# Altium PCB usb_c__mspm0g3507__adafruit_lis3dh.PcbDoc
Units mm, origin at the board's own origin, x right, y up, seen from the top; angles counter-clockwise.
Board outline 92 x 60 mm, 2 copper layers (Top, Bottom), stack 0 mm thick; 36 components, 30 nets, 196 pads, 60 vias.
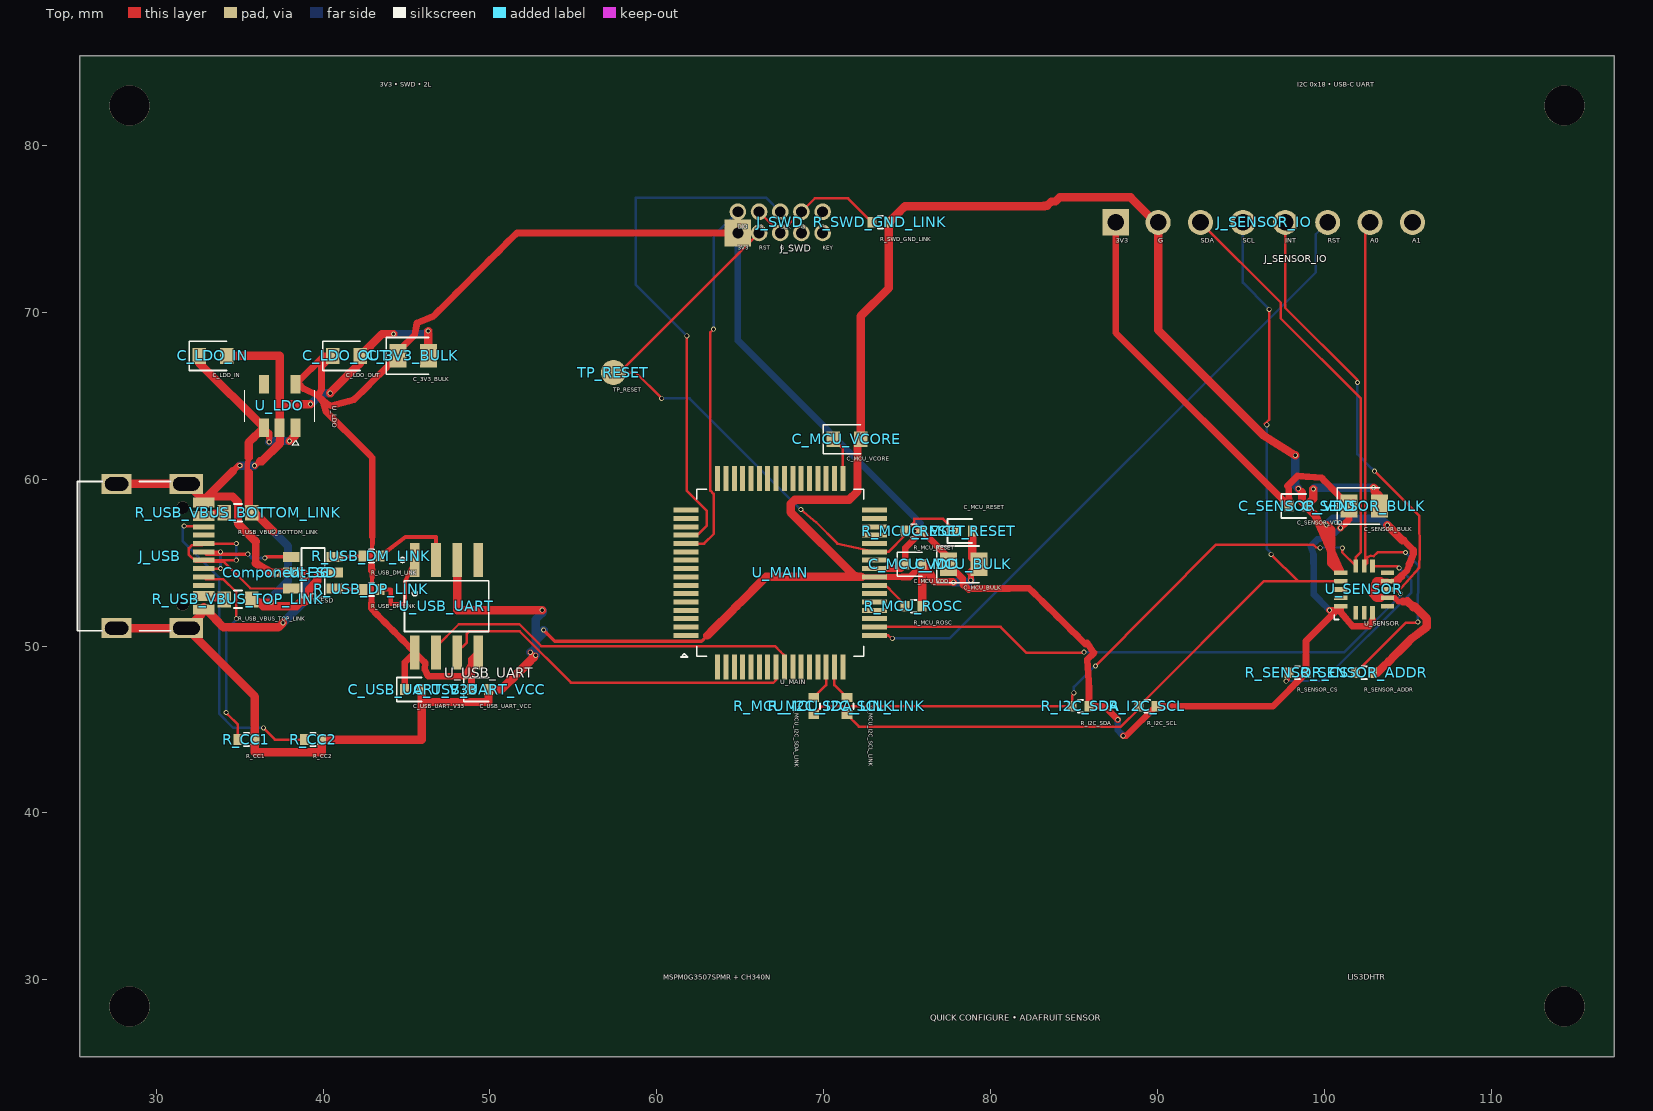
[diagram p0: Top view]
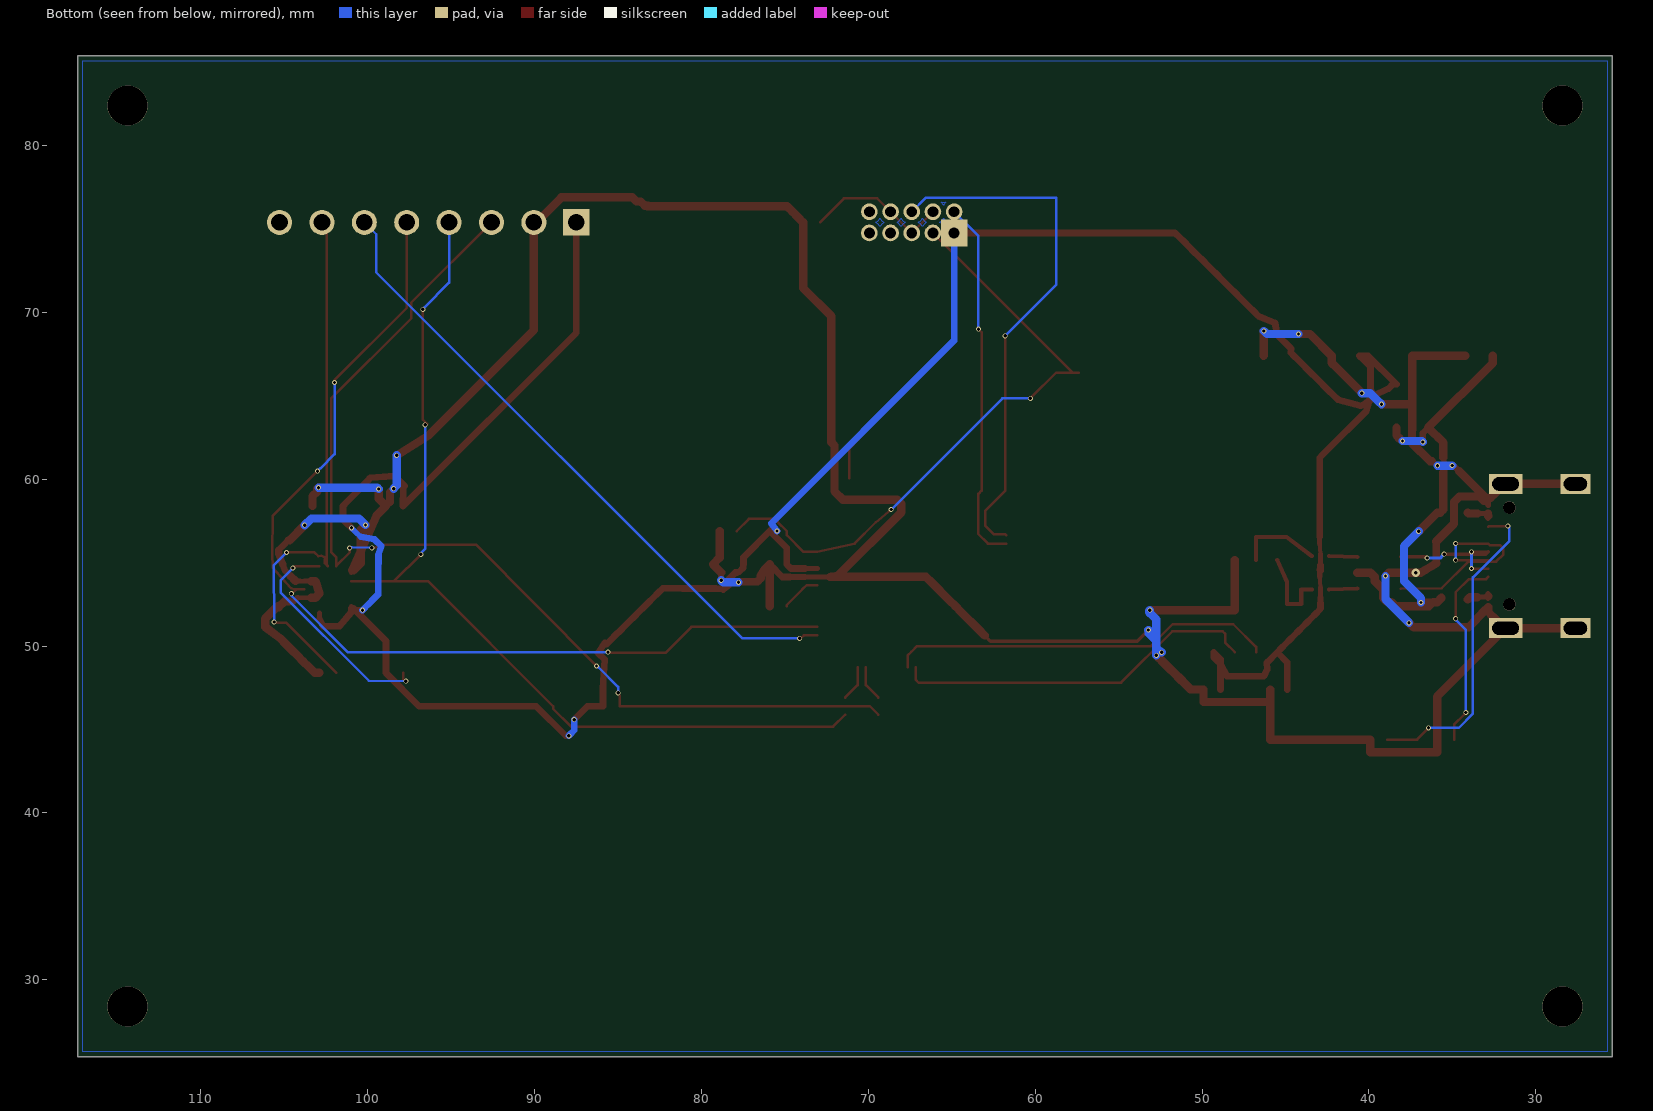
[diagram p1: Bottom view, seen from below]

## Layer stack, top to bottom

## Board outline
25.4,85.4 117.4,85.4 117.4,25.4 25.4,25.4

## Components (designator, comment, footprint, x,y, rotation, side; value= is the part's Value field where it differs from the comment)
C_3V3_BULK "" TSCIRCUIT-2.8500x1.4000mm 45.4,67.4 r0 top
C_LDO_IN "" TSCIRCUIT-2.4500x0.9500mm 33.4,67.4 r0 top
C_LDO_OUT "" TSCIRCUIT-2.4500x0.9500mm 41.4,67.4 r0 top
C_MCU_BULK "" TSCIRCUIT-2.8500x1.4000mm 78.4,54.9 r0 top
C_MCU_RESET "" TSCIRCUIT-1.5600x0.6400mm 78.4,56.9 r0 top
C_MCU_VCORE "" TSCIRCUIT-2.4500x0.9500mm 71.4,62.4 r0 top
C_MCU_VDD "" TSCIRCUIT-1.5600x0.6400mm 75.4,54.9 r0 top
C_SENSOR_BULK "" TSCIRCUIT-2.8500x1.4000mm 102.4,58.4 r0 top
C_SENSOR_VDD "" TSCIRCUIT-1.5600x0.6400mm 98.4,58.4 r0 top
C_USB_UART_V33 "" TSCIRCUIT-1.5600x0.6400mm 45.4,47.4 r0 top
C_USB_UART_VCC "" TSCIRCUIT-1.5600x0.6400mm 49.4,47.4 r0 top
Component-36 "" TSCIRCUIT-0.5000x0.5000mm 37.2,54.4 r0 top
J_SENSOR_IO "" TSCIRCUIT-19.2800x1.5000mm 96.4,75.4 r0 top
J_SWD "" TSCIRCUIT-6.0800x2.2700mm 67.4,75.4 r0 top
J_USB "" TSCIRCUIT-6.7732x9.8502mm 30.113,55.4 r90 top
R_CC1 "" TSCIRCUIT-1.5600x0.6400mm 35.4,44.4 r0 top
R_CC2 "" TSCIRCUIT-1.5600x0.6400mm 39.4,44.4 r0 top
R_I2C_SCL "" TSCIRCUIT-1.5600x0.6400mm 89.4,46.4 r0 top
R_I2C_SDA "" TSCIRCUIT-1.5600x0.6400mm 85.4,46.4 r0 top
R_MCU_I2C_SCL_LINK "" TSCIRCUIT-0.6400x1.5600mm 71.4,46.4 r270 top
R_MCU_I2C_SDA_LINK "" TSCIRCUIT-0.6400x1.5600mm 69.4,46.4 r270 top
R_MCU_RESET "" TSCIRCUIT-1.5600x0.6400mm 75.4,56.9 r0 top
R_MCU_ROSC "" TSCIRCUIT-1.5600x0.6400mm 75.4,52.4 r0 top
R_SENSOR_ADDR "" TSCIRCUIT-1.5600x0.6400mm 102.4,48.4 r0 top
R_SENSOR_CS "" TSCIRCUIT-1.5600x0.6400mm 98.4,48.4 r0 top
R_SWD_GND_LINK "" TSCIRCUIT-1.5600x0.6400mm 73.4,75.4 r0 top
R_USB_DM_LINK "" TSCIRCUIT-1.5600x0.6400mm 42.9,55.4 r0 top
R_USB_DP_LINK "" TSCIRCUIT-1.5600x0.6400mm 42.9,53.4 r0 top
R_USB_VBUS_BOTTOM_LINK "" TSCIRCUIT-2.4500x0.9500mm 34.9,58 r0 top
R_USB_VBUS_TOP_LINK "" TSCIRCUIT-2.4500x0.9500mm 34.9,52.8 r0 top
TP_RESET "" TSCIRCUIT-1.5000x1.5000mm 57.4,66.4 r0 top
U_ESD "" TSCIRCUIT-3.6000x2.5000mm 39.4,54.4 r0 top
U_LDO "" TSCIRCUIT-2.5000x3.7000mm 37.4,64.4 r270 top
U_MAIN "" TSCIRCUIT-12.8000x12.8000mm 67.4,54.4 r0 top
U_SENSOR "" TSCIRCUIT-3.6001x3.5998mm 102.4,53.4 r0 top
U_USB_UART "" TSCIRCUIT-4.3840x7.5712mm 47.4,52.4 r0 top

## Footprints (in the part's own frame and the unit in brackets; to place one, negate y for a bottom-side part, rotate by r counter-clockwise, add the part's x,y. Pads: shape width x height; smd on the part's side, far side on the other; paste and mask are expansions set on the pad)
TSCIRCUIT-0.5000x0.5000mm [mm]
TSCIRCUIT-0.6400x1.5600mm [mm]
  rect 0.54x0.64 smd: 1(-0.51,0) 2(0.51,0)
  silkscreen extent -0.15,-0.38 0.15,0.38
TSCIRCUIT-1.5000x1.5000mm [mm]
  round 1.5 smd: 1(0,0)
TSCIRCUIT-1.5600x0.6400mm [mm]
  rect 0.54x0.64 smd: 1(-0.51,0) 2(0.51,0)
  silkscreen extent -0.98,-0.72 0.51,0.72
TSCIRCUIT-2.4500x0.9500mm [mm]
  rect 0.8x0.95 smd: 1(-0.825,0) 2(0.825,0)
  silkscreen extent -1.42,-0.87 0.82,0.87
TSCIRCUIT-2.5000x3.7000mm [mm]
  rect 1.1x0.6 smd: 1(1.3,0.95) 2(1.3,0) 3(1.3,-0.95) 4(-1.3,-0.95) 5(-1.3,0.95)
  silkscreen extent -0.95,-2.1 2.35,2.1
TSCIRCUIT-2.8500x1.4000mm [mm]
  rect 1.025x1.4 smd: 1(-0.913,0) 2(0.913,0)
  silkscreen extent -1.63,-1.1 0.91,1.1
TSCIRCUIT-3.6000x2.5000mm [mm]
  rect 1x0.6 smd: 1(-1.3,-0.95) 2(-1.3,0) 3(-1.3,0.95) 4(1.3,0.95) 5(1.3,0) 6(1.3,-0.95)
  silkscreen extent -0.7,-1.49 0.7,1.49
TSCIRCUIT-3.6001x3.5998mm [mm]
  rect 0.8x0.28 smd: 1(-1.4,-1) 2(-1.4,-0.5) 3(-1.4,0) 4(-1.4,0.5) 5(-1.4,1) 9(1.4,1) 10(1.4,0.5) 11(1.4,0) 12(1.4,-0.5) 13(1.4,-1)
  rect 0.28x0.8 smd: 6(-0.5,1.4) 7(0,1.4) 8(0.5,1.4) 14(0.5,-1.4) 15(0,-1.4) 16(-0.5,-1.4)
  silkscreen extent -1.8,-1.8 -1.52,-1.52
TSCIRCUIT-4.3840x7.5712mm [mm]
  rect 0.574x2.036 smd: 1(-1.905,2.768) 2(-0.635,2.768) 3(0.635,2.768) 4(1.905,2.768) 5(1.905,-2.768) 6(0.635,-2.768) 7(-0.635,-2.768) 8(-1.905,-2.768)
  silkscreen extent -2.79,-1.52 2.53,2.92
TSCIRCUIT-6.0800x2.2700mm [mm]
  rect 1.6x1.6 hole 0.65: 1(-2.54,-0.635)
  round 1 hole 0.65: 2(-2.54,0.635) 3(-1.27,0.635) 4(0,0.635) 5(1.27,0.635) 6(2.54,0.635) 7(2.54,-0.635) 8(1.27,-0.635) 9(0,-0.635) 10(-1.27,-0.635)
TSCIRCUIT-6.7732x9.8502mm [mm]
  rect 0.3x1.3 smd: 1(-3.35,-2.737) 2(-3.05,-2.737) 3(-2.55,-2.737) 4(-2.25,-2.737) 5(-1.75,-2.737) 6(-1.25,-2.737) 7(-0.75,-2.737) 8(-0.25,-2.737) 9(0.25,-2.737) 10(0.75,-2.737) 11(1.25,-2.737) 12(1.75,-2.737) 13(2.55,-2.737) 14(2.25,-2.737) 15(3.35,-2.737) 16(3.05,-2.737)
  rect 1.2x2 hole 0.8 slot 1.6 at 90 deg: 17(-4.325,-1.693) 18(4.325,-1.693)
  rect 1.2x1.8 hole 0.8 slot 1.4 at 90 deg: 19(4.325,2.487) 20(-4.325,2.487)
  round 0.75 hole 0.75 unplated: NPTH-1(-2.9,-1.468) NPTH-2(2.9,-1.468)
  silkscreen extent -4.47,-0.75 4.47,4.83
TSCIRCUIT-12.8000x12.8000mm [mm]
  rect 1.5x0.3 smd: 1(-5.65,-3.75) 2(-5.65,-3.25) 3(-5.65,-2.75) 4(-5.65,-2.25) 5(-5.65,-1.75) 6(-5.65,-1.25) 7(-5.65,-0.75) 8(-5.65,-0.25) 9(-5.65,0.25) 10(-5.65,0.75) 11(-5.65,1.25) 12(-5.65,1.75) 13(-5.65,2.25) 14(-5.65,2.75) 15(-5.65,3.25) 16(-5.65,3.75) 33(5.65,3.75) 34(5.65,3.25) 35(5.65,2.75) 36(5.65,2.25) 37(5.65,1.75) 38(5.65,1.25) 39(5.65,0.75) 40(5.65,0.25) 41(5.65,-0.25) 42(5.65,-0.75) 43(5.65,-1.25) 44(5.65,-1.75) 45(5.65,-2.25) 46(5.65,-2.75) 47(5.65,-3.25) 48(5.65,-3.75)
  rect 0.3x1.5 smd: 17(-3.75,5.65) 18(-3.25,5.65) 19(-2.75,5.65) 20(-2.25,5.65) 21(-1.75,5.65) 22(-1.25,5.65) 23(-0.75,5.65) 24(-0.25,5.65) 25(0.25,5.65) 26(0.75,5.65) 27(1.25,5.65) 28(1.75,5.65) 29(2.25,5.65) 30(2.75,5.65) 31(3.25,5.65) 32(3.75,5.65) 49(3.75,-5.65) 50(3.25,-5.65) 51(2.75,-5.65) 52(2.25,-5.65) 53(1.75,-5.65) 54(1.25,-5.65) 55(0.75,-5.65) 56(0.25,-5.65) 57(-0.25,-5.65) 58(-0.75,-5.65) 59(-1.25,-5.65) 60(-1.75,-5.65) 61(-2.25,-5.65) 62(-2.75,-5.65) 63(-3.25,-5.65) 64(-3.75,-5.65)
  silkscreen extent -5.95,-5.05 5,5
TSCIRCUIT-19.2800x1.5000mm [mm]
  rect 1.6x1.6 hole 1: 1(-8.89,0)
  round 1.5 hole 1: 2(-6.35,0) 3(-3.81,0) 4(-1.27,0) 5(1.27,0) 6(3.81,0) 7(6.35,0) 8(8.89,0)

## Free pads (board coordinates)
  round 2.4 hole 2.4 unplated: NPTH-3(28.4,28.4) NPTH-4(114.4,28.4) NPTH-5(28.4,82.4) NPTH-6(114.4,82.4)

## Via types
v1: diameter 0.3, hole 0.2, Top to Bottom, 59 vias
v2: diameter 0.5, hole 0.2, Top to Bottom, 1 vias

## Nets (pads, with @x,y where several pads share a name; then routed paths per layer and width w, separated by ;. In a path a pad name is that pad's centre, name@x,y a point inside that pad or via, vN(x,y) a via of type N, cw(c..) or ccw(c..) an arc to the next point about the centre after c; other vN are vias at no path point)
".J_SWD > .pin2 to .U_MAIN > .pin12": J_SWD.2 U_MAIN.12 | length 22
  Top w0.15: U_MAIN.12 62.836,56.15 63.412,56.726 63.404,59.125 63.215,59.325 63.217,68.817 v1(63.4,69)
  Bottom w0.15: v1(63.4,69) 63.4,69.14 63.4,74.575 J_SWD.2
".J_SWD > .pin4 to .U_MAIN > .pin13": J_SWD.4 U_MAIN.13 | length 31.9
  Top w0.15: U_MAIN.13 61.811,56.711 62.49,56.711 63.008,57.229 63.008,58.102 61.8,59.31 v1(61.8,68.6)
  Bottom w0.15: v1(61.8,68.6) 61.756,68.644 58.745,71.655 58.745,76.868 66.567,76.868 J_SWD.4
".U_MAIN > .pin42 to .R_MCU_ROSC > .pin1": R_MCU_ROSC.1 U_MAIN.42 | length 2.4
  Top w0.15: U_MAIN.42 73.701,53.651 73.958,53.413 74.89,52.46 R_MCU_ROSC.1
GND: C_3V3_BULK.2 C_LDO_IN.2 C_LDO_OUT.2 C_MCU_BULK.2 C_MCU_RESET.2 C_MCU_VCORE.2 C_MCU_VDD.2 C_SENSOR_BULK.2 C_SENSOR_VDD.2 C_USB_UART_V33.2 C_USB_UART_VCC.2 J_SENSOR_IO.2 J_USB.1 J_USB.2 J_USB.15 J_USB.16 J_USB.17 J_USB.18 J_USB.19 J_USB.20 R_CC1.2 R_CC2.2 R_MCU_ROSC.2 R_SENSOR_ADDR.2 R_SWD_GND_LINK.2 U_ESD.2 U_LDO.2 U_MAIN.41 U_SENSOR.5 U_SENSOR.10 U_SENSOR.12 U_USB_UART.3 | length 241.6
  Top w0.2: v1(53.215,50.967) 53.554,50.628 53.893,50.289 54.381,50.289 54.87,50.289 55.358,50.289 55.846,50.289 56.334,50.289 56.823,50.289 57.311,50.289 57.799,50.289 58.288,50.289 58.776,50.289 59.264,50.289 59.752,50.289 60.241,50.289 60.729,50.289 61.217,50.289 61.706,50.289 62.194,50.289 62.682,50.289 63.033,50.64
  Top w0.275: J_USB.16 J_USB.15@33.109,58.71
  Top w0.28: U_SENSOR.5@100.86,54.54 U_SENSOR.5 U_SENSOR.5@100.938,54.54 ; U_SENSOR.12@103.4,52.9 U_SENSOR.12 103.988,52.9 104.081,52.9 104.175,52.9 U_SENSOR.12@104.2,52.9 ; U_SENSOR.10@103.4,53.9 U_SENSOR.10 104.069,53.9 104.338,53.9
  Top w0.3: J_USB.1@32.699,51.9 J_USB.1 J_USB.1@32.849,52.2 ; J_USB.15@32.699,58.9 J_USB.15 ; J_USB.2 J_USB.1@32.994,52.2 ; J_USB.16@32.849,58.6 J_USB.15 ; J_USB.15@32.999,58.9 J_USB.15 ; U_MAIN.41@73.8,54.15 73.706,54.15 73.612,54.15 73.519,54.15 73.425,54.15 73.331,54.15 73.237,54.15 73.144,54.15 U_MAIN.41 ; U_MAIN.41 72.627,54.15 72.3,54.15 72.585,54.15 U_MAIN.41
  Top w0.325: J_USB.16 J_USB.16@32.849,58.6 ; v1(35.89,60.817) 35.911,60.796 v1@35.913,60.796 ; v1(52.425,49.625) v1@52.64,49.349 ; 52.617,49.315 52.617,49.325 v1(52.74,49.449) ; 104.252,52.873 104.315,52.798 104.387,52.735 104.458,52.682
  Top w0.35: v1@35.913,60.796 36.216,61.092 ; 104.2,52.9 104.225,52.9 104.252,52.873
  Top w0.375: 34.578,60.479 34.924,60.825 v1(35.007,60.825) ; U_MAIN.41@73.8,54.15 74.253,54.15 74.707,54.15 ; v1(78.825,53.948) C_MCU_BULK.2@78.825,54.413 ; v1(98.454,59.443) 98.674,59.223 ; 104.458,52.682 104.46,52.682 104.725,52.682 ; 104.65,54.213 104.963,54.525 105.087,54.858 ; 104.775,56.337 105.056,56.056 105.338,55.775
  Top w0.4: 37.2,54.4 U_ESD.2@37.6,54.4 ; 74.707,54.15 75.16,54.15 75.41,54.4 75.66,54.65 C_MCU_VDD.2
  Top w0.425: C_SENSOR_VDD.2@98.674,58.636 C_SENSOR_VDD.2 ; 105.087,54.858 105.212,55.192 105.338,55.525 105.338,55.775
  Top w0.437: 35.963,55.4 35.963,55.838 35.963,56.275
  Top w0.45: 35.963,54.963 35.963,55.4 ; 76.65,53.869 76.946,53.864 77.338,53.864 77.73,53.864 77.749,53.86 v1(77.781,53.828) ; 104.693,56.337 104.775,56.337
  Top w0.475: 71.656,54.15 72.12,54.15 72.3,54.15 72.205,54.15 ; 76.453,54.066 76.65,53.869 ; 104.338,53.9 104.65,54.213 ; 104.725,52.682 104.991,52.682
  Top w0.5: J_USB.20 J_USB.17 ; J_USB.19 J_USB.18 31.874,59.725 32.474,59.125 32.699,58.9 ; 32.699,51.9 32.474,51.675 31.874,51.075 J_USB.17 ; J_USB.1@32.849,52.2 J_USB.2 ; J_USB.1@32.994,52.2 34.028,51.131 37.321,51.131 v1(37.592,51.402) ; 32.999,58.9 34.578,60.479 ; J_USB.15@33.109,58.71 33.368,58.969 34.581,58.969 34.9,58.65 34.9,57.338 35.963,56.275 ; C_LDO_IN.2 37.4,67.4 U_LDO.2 ; 35.963,54.963 36.274,54.775 36.586,54.588 36.897,54.4 37.2,54.4 38.8,54.4 v1(39,54.2) ; 36.216,61.092 36.342,61.092 37.4,62.15 37.414,62.686 U_LDO.2 ; v1(39.244,64.505) 37.4,64.505 U_LDO.2 ; v1(40.421,65.166) 40.416,65.166 40.422,65.17 40.723,65.471 41.023,65.773 41.324,66.075 41.624,66.377 41.925,66.679 42.225,66.981 C_LDO_OUT.2 43.534,68.709 v1(44.222,68.709) ; v1(46.293,68.892) 46.293,67.419 C_3V3_BULK.2 ; U_USB_UART.3 48.035,52.154 v1(53.131,52.154) ; 52.617,49.315 52.297,48.996 51.978,48.677 51.659,48.358 51.34,48.038 51.021,47.719 50.702,47.4 50.306,47.4 C_USB_UART_VCC.2 ; v1@52.64,49.349 52.603,49.349 52.278,49.024 51.953,48.699 51.628,48.374 51.304,48.05 50.979,47.725 50.654,47.4 50.282,47.4 C_USB_UART_VCC.2 ; 63.033,50.64 63.384,50.991 63.735,51.342 64.086,51.693 64.437,52.044 64.788,52.395 65.139,52.746 65.49,53.097 65.841,53.448 66.192,53.799 66.543,54.15 67.008,54.15 67.473,54.15 67.937,54.15 68.402,54.15 68.867,54.15 69.332,54.15 69.797,54.15 70.261,54.15 70.726,54.15 71.191,54.15 71.656,54.15 ; 72.205,54.15 71.994,54.15 71.947,54.197 71.853,54.197 68.025,58.025 68.025,58.525 68.275,58.775 71.525,58.775 72.025,59.275 72.025,62.025 72.225,62.225 C_MCU_VCORE.2 72.225,62.892 72.225,63.384 72.225,63.876 72.225,64.368 72.225,64.86 72.225,65.352 72.225,65.844 72.225,66.336 72.225,66.828 72.225,67.32 72.225,67.812 72.225,68.303 72.225,68.795 72.225,69.287 72.225,69.779 73.91,71.464 R_SWD_GND_LINK.2 74.232,75.722 74.554,76.044 74.876,76.366 74.951,76.366 75.438,76.366 75.925,76.366 76.413,76.366 76.9,76.366 77.387,76.366 77.875,76.366 78.362,76.366 78.849,76.366 79.337,76.366 79.824,76.366 80.311,76.366 80.799,76.366 81.286,76.366 81.773,76.366 82.261,76.366 82.748,76.366 83.235,76.366 83.202,76.4 83.4,76.4 83.65,76.65 83.9,76.65 84.15,76.9 88.4,76.9 89.9,75.4 J_SENSOR_IO.2 90.05,74.93 90.05,74.46 90.05,73.989 90.05,73.519 90.05,73.049 90.05,72.579 90.05,72.109 90.05,71.639 90.05,71.168 90.05,70.698 90.05,70.228 90.05,69.758 90.05,68.95 96.4,62.6 v1(98.271,61.436) ; R_MCU_ROSC.2 C_MCU_VDD.2 76.255,54.555 76.453,54.212 76.453,54.066 ; C_MCU_BULK.2@78.825,54.413 79.061,54.648 C_MCU_BULK.2 78.91,55.303 C_MCU_RESET.2 ; C_SENSOR_VDD.2@98.674,58.636 98.674,59.223 ; v1(99.35,59.42) 99.35,58.84 C_SENSOR_VDD.2 99.186,58.124 99.462,57.848 100.938,54.54 ; v1(100.137,57.262) 100.425,56.974 100.425,54.975 100.712,54.687 U_SENSOR.5@100.86,54.54 ; R_SENSOR_ADDR.2 103.177,48.4 103.526,48.746 103.874,49.093 104.223,49.439 104.571,49.786 104.92,50.132 105.268,50.479 106.15,51.15 106.15,51.65 105.4,52.4 105.341,52.336 104.991,52.682 ; v1(102.957,59.496) 103.022,59.431 103.022,59.28 103.313,58.989 C_SENSOR_BULK.2 ; U_SENSOR.12@103.4,52.9 103.15,52.9 102.9,53.15 103.15,53.9 U_SENSOR.10@103.4,53.9 ; v1(103.782,57.249) 104.693,56.337 ; J_USB.17 35.91,46.971 R_CC1.2 35.91,43.65 39.91,43.65 R_CC2.2 40.41,44.4 40.91,44.4 45.91,44.4 C_USB_UART_V33.2 45.91,46.65 49.91,46.65 C_USB_UART_VCC.2
  Bottom w0.5: v1(35.007,60.825) 35.015,60.817 v1(35.89,60.817) ; v1(37.592,51.402) 39,52.81 v1(39,54.2) ; v1(39.244,64.505) 39.347,64.608 39.372,64.608 39.644,64.881 39.917,65.153 40.169,65.159 v1(40.421,65.166) ; v1(44.222,68.709) 46.111,68.709 v1(46.293,68.892) ; v1(52.425,49.625) 52.74,49.879 ; v1(52.74,49.449) 52.74,49.88 ; v1(53.131,52.154) 53.164,52.121 53.164,52.022 52.952,51.811 52.74,51.599 52.74,51.169 52.74,50.739 52.74,50.309 52.74,49.879 ; v1(53.215,50.967) 53.191,50.943 53.191,50.761 52.966,50.536 52.74,50.311 52.74,49.88 ; v1(77.781,53.828) 78.705,53.828 v1(78.825,53.948) ; v1(98.271,61.436) 98.271,59.626 v1(98.454,59.443) ; v1(99.35,59.42) 99.426,59.496 v1(102.957,59.496) ; v1(100.137,57.262) 100.525,57.65 100.65,57.65 103.381,57.65 v1(103.782,57.249)
MAIN_RESET: C_MCU_RESET.1 J_SWD.10 R_MCU_RESET.1 TP_RESET.1 U_MAIN.38 | length 38.3
  Top w0.15: v1(60.288,64.85) 60.277,64.861 58.738,66.4 TP_RESET.1 57.765,66.4 J_SWD.10 ; v1(68.634,58.195) 69.555,57.424 70.823,56.15 U_MAIN.38 73.889,55.65 74.889,56.651 R_MCU_RESET.1@74.889,56.899 ; R_MCU_RESET.1 75.442,57.452 75.442,57.636 77.166,57.628 C_MCU_RESET.1
  Bottom w0.15: v1(60.288,64.85) 61.965,64.85 68.556,58.259 68.562,58.259 v1(68.634,58.195)
MCU_I2C_SCL_LOCAL: R_MCU_I2C_SCL_LINK.1 U_MAIN.50 | length 2.2
  Top w0.15: U_MAIN.50 70.65,47.66 R_MCU_I2C_SCL_LINK.1
MCU_I2C_SDA_LOCAL: R_MCU_I2C_SDA_LINK.1 U_MAIN.51 | length 2.2
  Top w0.15: R_MCU_I2C_SDA_LINK.1 70.15,47.66 U_MAIN.51
MSPM0_VCORE: C_MCU_VCORE.1 U_MAIN.32 | length 2.6
  Top w0.15: C_MCU_VCORE.1 71.15,61.825 U_MAIN.32
SENSOR_ADDR0: J_SENSOR_IO.7 R_SENSOR_ADDR.1 U_SENSOR.7 | length 33.3
  Top w0.15: R_SENSOR_ADDR.1 104.906,51.416 105.621,51.416 v1(105.613,51.45) ; J_SENSOR_IO.7 102.461,75.11 102.463,55.025 102.46,54.86 U_SENSOR.7 102.57,54.974 102.57,55.202 102.563,55.322 102.794,55.422 102.966,55.39 103.199,55.618 v1(104.871,55.618)
  Bottom w0.15: v1(104.871,55.618) 104.887,55.602 105.647,54.842 v1(105.613,51.45)
SENSOR_ADDR1: J_SENSOR_IO.8
SENSOR_CS: R_SENSOR_CS.1 U_SENSOR.8 | length 13.7
  Top w0.15: v1(97.725,47.9) 97.89,47.976 97.89,48.15 R_SENSOR_CS.1 ; U_SENSOR.8 104.376,54.8 v1(104.492,54.684)
  Bottom w0.15: v1(97.725,47.9) 99.943,47.929 105.233,53.219 105.233,53.943 104.51,54.666 v1(104.492,54.684)
SENSOR_INT: J_SENSOR_IO.5 U_MAIN.47 U_SENSOR.11 | length 61.2
  Top w0.15: U_MAIN.47 80.608,51.15 82.158,49.6 85.616,49.6 v1@85.645,49.629 ; v1(85.606,49.643) v1@85.646,49.629 ; J_SENSOR_IO.5 97.67,70.27 101.998,65.943 101.998,65.802 v1(101.996,65.8) ; v1(103.02,60.493) 105.707,57.806 105.734,55.552 105.707,54.707 104.598,53.473 104.4,53.4 U_SENSOR.11 104.267,53.4 v1(104.582,53.15)
  Bottom w0.15: v1(85.606,49.643) 101.199,49.632 104.561,52.994 104.561,53.106 v1(104.582,53.15) ; v1(101.996,65.8) 101.996,61.507 102.849,60.654 102.859,60.654 v1(103.02,60.493)
SENSOR_RESET: J_SENSOR_IO.6 U_MAIN.48 | length 38.9
  Top w0.15: U_MAIN.48 73.868,50.65 73.997,50.522 74.059,50.522 v1(74.116,50.465)
  Bottom w0.15: v1(74.116,50.465) 77.553,50.465 99.496,72.408 99.496,74.686 J_SENSOR_IO.6
SENSOR_SCL: J_SENSOR_IO.4 R_I2C_SCL.1 R_MCU_I2C_SCL_LINK.2 U_SENSOR.4 | length 59.3
  Top w0.15: R_MCU_I2C_SCL_LINK.2 72.112,45.178 87.819,45.178 88.89,46.249 R_I2C_SCL.1 96.39,53.9 U_SENSOR.4 98.42,53.9 v1(96.82,55.5) ; v1(96.565,63.261) 96.508,63.318 96.45,63.318 96.703,63.571 v1(96.703,70.192)
  Bottom w0.15: J_SENSOR_IO.4 95.13,71.79 96.643,70.277 96.643,70.252 v1(96.703,70.192) ; v1(96.565,63.261) 96.565,55.824 96.785,55.604 96.785,55.535 v1(96.82,55.5)
SENSOR_SDA: J_SENSOR_IO.3 R_I2C_SDA.1 R_MCU_I2C_SDA_LINK.2 U_SENSOR.6 | length 62.8
  Top w0.15: R_MCU_I2C_SDA_LINK.2 69.91,46.4 R_I2C_SDA.1 84.89,47.037 84.97,47.117 84.97,47.17 v1(85,47.2) ; v1(86.292,48.815) 93.513,56.091 98.059,56.091 99.343,56.091 99.494,55.94 v1(99.758,55.89) ; J_SENSOR_IO.3 97.4,70.59 97.4,69.643 102.197,64.843 102.198,55.632 101.9,55.332 U_SENSOR.6 101.085,55.615 v1(101.085,55.884)
  Bottom w0.15: v1(85,47.2) 85,47.557 86.161,48.718 86.161,48.739 v1(86.292,48.815) ; v1(99.758,55.89) 100.963,55.94 101.029,55.94 v1(101.085,55.884)
swd-ground-1-to-2: J_SWD.3 J_SWD.5 J_SWD.9 R_SWD_GND_LINK.1 | length 8.8
  Top w0.15: J_SWD.3 J_SWD.9 J_SWD.5 69.481,76.846 71.471,76.846 71.471,76.819 R_SWD_GND_LINK.1
UART_MSP_RX: U_MAIN.57 U_USB_UART.6 | length 22.1
  Top w0.15: U_USB_UART.6 48.6,50.197 48.6,50.724 48.767,50.891 51.779,50.892 54.854,47.815 66.991,47.808 67.15,47.975 U_MAIN.57
UART_MSP_TX: U_MAIN.56 U_USB_UART.7 | length 23.2
  Top w0.15: U_USB_UART.7 46.765,49.952 48.128,51.315 51.766,51.315 53.075,50.006 67.085,50.006 67.431,49.659 67.65,49.441 U_MAIN.56
usb-dm-device: R_USB_DM_LINK.1 U_ESD.4 | length 1.7
  Top w0.25: U_ESD.4 R_USB_DM_LINK.1
usb-dm-port-tie: J_USB.7 J_USB.9 U_ESD.3 | length 8.4
  Top w0.15: J_USB.7 v1(33.85,54.65) ; J_USB.9 v1(33.85,55.65)
  Top w0.2: J_USB.9 32.983,55.516 v1(35.49,55.516) ; v1(36.508,55.282) 36.576,55.35 36.6,55.35 U_ESD.3
  Bottom w0.15: v1(33.85,54.65) v1(33.85,55.65)
  Bottom w0.2: v1(35.49,55.516) 35.571,55.435 35.573,55.435 35.726,55.282 v1(36.508,55.282)
usb-dm-uart: R_USB_DM_LINK.2 U_USB_UART.2 | length 5.1
  Top w0.25: R_USB_DM_LINK.2 44.95,56.55 46.765,56.55 U_USB_UART.2
usb-dp-device: R_USB_DP_LINK.1 U_ESD.6 | length 1.7
  Top w0.25: U_ESD.6 R_USB_DP_LINK.1
usb-dp-port-tie: J_USB.8 J_USB.10 U_ESD.1 | length 13.3
  Top w0.15: J_USB.8 v1(34.8,55.15) ; v1(34.8,56.15) J_USB.10 32.755,56.056 32.141,56.056 31.95,55.865 31.938,55.488 32.379,55.062 34.02,55.067 35.637,53.469 U_ESD.1
  Bottom w0.15: v1(34.8,55.15) v1(34.8,56.15)
usb-dp-uart: R_USB_DP_LINK.2 U_USB_UART.1 | length 5.1
  Top w0.25: R_USB_DP_LINK.2 44.05,53.4 44.05,52.53 44.9,52.53 44.9,53.85 U_USB_UART.1
USB_CC1: J_USB.6 R_CC1.1 | length 11.7
  Top w0.15: J_USB.6 32.979,54.02 34.01,54.02 34.8,53.23 v1(34.8,51.653) ; v1(34.187,46.022) 34.285,45.924 34.285,45.899 34.89,45.294 R_CC1.1
  Bottom w0.15: v1(34.187,46.022) 34.187,50.972 34.752,51.537 34.752,51.552 v1(34.8,51.653)
USB_CC2: J_USB.12 R_CC2.1 | length 19.2
  Top w0.15: v1(31.668,57.197) 32.802,57.197 J_USB.12 ; v1(36.424,45.106) 36.422,45.089 36.426,45.089 37.115,44.4 R_CC2.1
  Bottom w0.15: v1(31.668,57.197) 31.594,57.123 31.594,57.047 31.578,57.031 31.578,56.304 33.761,54.122 33.761,45.961 34.616,45.106 v1(36.424,45.106)
USB_VBUS_BOTTOM_LOCAL: J_USB.13 J_USB.14 R_USB_VBUS_BOTTOM_LINK.1 | length 1.5
  Top w0.3: J_USB.14 J_USB.14@32.849,57.8 ; J_USB.13 32.927,57.95 33.005,57.95 33.083,57.95 33.161,57.95 33.239,57.95 33.317,57.95 33.394,57.95 33.472,57.95 33.499,57.95
  Top w0.475: J_USB.13@32.849,57.8 J_USB.13 ; 33.499,57.95 R_USB_VBUS_BOTTOM_LINK.1@33.762,57.95
  Top w0.5: R_USB_VBUS_BOTTOM_LINK.1@33.762,57.95 34.025,57.95 R_USB_VBUS_BOTTOM_LINK.1
USB_VBUS_TOP_LOCAL: J_USB.3 J_USB.4 R_USB_VBUS_TOP_LINK.1 | length 1.6
  Top w0.3: J_USB.4 32.849,53 J_USB.3 32.944,52.959 33.033,52.939 33.499,52.939
  Top w0.5: 33.499,52.939 33.675,52.939 33.936,52.939 R_USB_VBUS_TOP_LINK.1
VBUS5: C_LDO_IN.1 R_USB_VBUS_BOTTOM_LINK.2 R_USB_VBUS_TOP_LINK.2 U_ESD.5 U_LDO.1 U_LDO.3 | length 29.5
  Top w0.325: 35.537,61.305 35.462,60.869 35.462,60.4 35.538,60.411 ; v1(36.763,62.238) 36.781,62.494
  Top w0.375: U_LDO.3 36.781,62.769
  Top w0.4: 36.781,62.494 36.781,62.769
  Top w0.45: v1(37.981,62.292) 38.121,62.432 38.151,62.432
  Top w0.5: C_LDO_IN.1 32.575,66.975 U_LDO.3 36.145,62.799 35.84,62.499 35.535,62.198 35.536,61.752 35.537,61.305 ; 35.538,60.411 35.538,58.187 R_USB_VBUS_BOTTOM_LINK.2 35.895,58 36.174,57.721 36.453,57.442 36.733,57.162 37.012,56.883 v1(37.017,56.878) ; v1(36.88,52.615) 36.395,52.615 35.91,52.615 R_USB_VBUS_TOP_LINK.2 35.65,52.875 35.65,52.9 35.9,52.65 36.15,52.65 36.4,52.4 38.4,52.4 38.65,52.65 38.9,52.65 39.15,52.9 39.15,53.4 39.65,53.9 39.65,54.15 39.9,54.4 U_ESD.5 ; 38.151,62.432 38.35,62.631 U_LDO.1
  Bottom w0.5: v1(36.763,62.238) 36.817,62.292 v1(37.981,62.292) ; v1(36.88,52.615) 36.88,52.88 37.9,53.9 37.9,55.995 v1(37.017,56.878)
VCC_3V3: C_3V3_BULK.1 C_LDO_OUT.1 C_MCU_BULK.1 C_MCU_VDD.1 C_SENSOR_BULK.1 C_SENSOR_VDD.1 C_USB_UART_V33.1 C_USB_UART_VCC.1 J_SENSOR_IO.1 J_SWD.1 R_I2C_SCL.2 R_I2C_SDA.2 R_MCU_RESET.2 R_SENSOR_CS.2 U_LDO.5 U_MAIN.40 U_SENSOR.1 U_SENSOR.14 U_USB_UART.5 U_USB_UART.8 | length 170.1
  Top w0.25: 42.9,53.525 42.923,53.859 42.947,54.193 ; 42.9,55.525 42.923,55.845 42.947,56.166
  Top w0.275: 42.9,52.9 42.9,53.212 42.9,53.525 ; 42.9,54.858 42.9,55.192 42.9,55.525
  Top w0.28: U_SENSOR.1@101,52.26 U_SENSOR.1 ; U_SENSOR.14@102.9,51.6 U_SENSOR.14 ; U_SENSOR.1 100.86,52.26 U_SENSOR.1
  Top w0.3: 42.947,56.166 42.947,56.56 ; U_MAIN.40 73.15,54.65 73.25,54.65 73.35,54.65 73.45,54.65 73.55,54.65 73.65,54.65 73.75,54.65 U_MAIN.40@73.8,54.65
  Top w0.312: 42.947,54.193 42.947,54.587
  Top w0.387: 42.9,52.587 42.9,52.9
  Top w0.4: 42.9,52.587 42.9,52.275 42.947,52.22 42.947,52.18 43.201,51.926 43.456,51.671 43.711,51.416 43.966,51.161 44.221,50.906 44.476,50.651 44.73,50.397 44.985,50.142 45.24,49.887 U_USB_UART.8 ; 42.9,54.858 42.9,54.525 42.947,54.587 ; 42.947,56.56 42.947,56.955 42.947,57.35 42.947,57.744 42.947,58.139 42.947,58.533 42.947,58.928 42.947,59.322 42.947,59.717 42.947,60.112 42.947,60.506 42.947,60.901 42.947,61.295 42.825,61.419 42.558,61.687 42.29,61.955 42.023,62.222 41.755,62.49 41.488,62.758 41.22,63.026 40.953,63.294 40.685,63.561 40.418,63.829 40.15,64.097 40,64.6 39.705,65.03 38.813,65.436 38.546,65.704 U_LDO.5 40.05,67.4 C_LDO_OUT.1 40.306,67.135 40.038,66.87 39.9,66.8 39.9,66.45 39.9,66.1 39.9,65.75 39.9,65.4 39.7,65 40.2,64.55 40.5,64.4 40.841,64.493 41.181,64.587 41.522,64.68 41.863,64.774 42.125,65.036 42.388,65.299 42.65,65.562 42.913,65.824 43.175,66.087 43.438,66.349 43.7,66.612 43.963,66.875 44.225,67.137 C_3V3_BULK.1 44.677,67.589 44.663,67.835 44.942,68.112 45.22,68.389 45.498,68.667 45.629,69.373 46.61,69.776 46.889,70.053 47.167,70.331 47.445,70.608 47.723,70.885 48.001,71.163 48.279,71.44 48.558,71.717 48.836,71.995 49.114,72.272 49.392,72.549 49.67,72.827 49.948,73.104 50.226,73.381 50.505,73.659 50.783,73.936 51.061,74.214 51.339,74.491 51.617,74.768 52.007,74.768 52.396,74.768 52.786,74.768 53.175,74.768 53.565,74.768 53.954,74.768 54.344,74.768 54.733,74.767 55.123,74.767 55.512,74.767 55.902,74.767 56.291,74.767 56.681,74.767 57.07,74.767 57.46,74.767 57.849,74.767 58.239,74.767 58.628,74.766 59.018,74.766 59.407,74.766 59.797,74.766 60.186,74.766 60.576,74.766 60.965,74.766 61.355,74.766 61.744,74.766 62.134,74.766 62.523,74.766 62.913,74.765 63.302,74.765 63.692,74.765 64.081,74.765 64.471,74.765 J_SWD.1 ; C_USB_UART_V33.1 44.89,49.027 U_USB_UART.8 ; C_USB_UART_VCC.1 48.89,49.217 U_USB_UART.5 49.305,49.345 49.093,49.129 48.881,48.912 48.5,48.2 46.3,48.2 46.1,48.6 46.115,49.012 45.908,49.219 45.702,49.425 U_USB_UART.8 ; U_MAIN.40@73.8,54.65 73.85,54.65 74.64,54.65 C_MCU_VDD.1 74.89,55.88 R_MCU_RESET.2 ; v1(75.475,56.9) 75.822,56.988 R_MCU_RESET.2 ; J_SENSOR_IO.1 87.51,68.78 C_SENSOR_VDD.1 97.888,58.742 97.886,59.085 97.884,59.427 97.8,59.6 98.4,60.2 99.861,60.087 100.001,59.924 100.249,59.67 100.497,59.416 100.744,59.162 100.992,58.908 101.24,58.654 C_SENSOR_BULK.1 101.488,58.133 101.488,57.866 101.488,57.599 101.241,57.352 100.994,57.105 v1(100.983,57.087) ; v1(87.63,45.592) 87.591,45.631 87.591,45.648 86.839,46.4 R_I2C_SDA.2 85.907,46.769 85.904,47.138 85.9,47.507 85.897,47.876 85.8,49.2 86.2,49.6 85.8,50.2 85.712,50.105 85.43,50.385 85.148,50.665 84.866,50.945 84.584,51.225 84.301,51.504 84.019,51.784 83.737,52.064 83.455,52.344 83.173,52.624 82.891,52.904 82.609,53.183 82.327,53.463 81.927,53.462 81.527,53.461 81.128,53.46 80.728,53.459 80.328,53.458 79.929,53.456 79.529,53.455 79.129,53.454 78.7,53.4 78.33,53.69 78.33,54.05 77.97,54.41 77.9,54.4 77.738,54.464 77.489,54.717 C_MCU_BULK.1 77.488,55.323 R_MCU_RESET.2 ; v1(87.951,44.628) 88.138,44.628 R_I2C_SCL.2 96.92,46.39 R_SENSOR_CS.2 98.91,50.31 100.86,52.26 100.754,52.154 100.535,52.154 v1(100.316,52.154) ; 101,52.26 101,52.031 101.7,51.2 102.7,51.2 102.9,51.6
  Bottom w0.312: 100.432,56.556 100.708,56.821 v1(100.983,57.087)
  Bottom w0.4: J_SWD.1 64.86,68.322 75.822,57.361 v1(75.475,56.9) ; v1(87.63,45.592) 87.63,44.959 87.889,44.7 87.889,44.69 v1(87.951,44.628) ; v1(100.316,52.154) 100.183,52.287 100.183,52.304 99.917,52.568 99.651,52.832 99.385,53.096 99.381,53.496 99.376,53.896 99.372,54.296 99.368,54.696 99.364,55.096 99.36,55.496 99.2,56 99.6,56.4 100.432,56.556
pads on no net: J_SWD.6 J_SWD.7 J_SWD.8 J_USB.5 J_USB.11 J_USB.NPTH-1 J_USB.NPTH-2 U_LDO.4 U_MAIN.1 U_MAIN.2 U_MAIN.3 U_MAIN.4 U_MAIN.5 U_MAIN.6 U_MAIN.7 U_MAIN.8 U_MAIN.9 U_MAIN.10 U_MAIN.11 U_MAIN.14 U_MAIN.15 U_MAIN.16 U_MAIN.17 U_MAIN.18 U_MAIN.19 U_MAIN.20 U_MAIN.21 U_MAIN.22 U_MAIN.23 U_MAIN.24 U_MAIN.25 U_MAIN.26 U_MAIN.27 U_MAIN.28 U_MAIN.29 U_MAIN.30 U_MAIN.31 U_MAIN.33 U_MAIN.34 U_MAIN.35 U_MAIN.36 U_MAIN.37 U_MAIN.39 U_MAIN.43 U_MAIN.44 U_MAIN.45 U_MAIN.46 U_MAIN.49 U_MAIN.52 U_MAIN.53 U_MAIN.54 U_MAIN.55 U_MAIN.58 U_MAIN.59 U_MAIN.60 U_MAIN.61 U_MAIN.62 U_MAIN.63 U_MAIN.64 U_SENSOR.2 U_SENSOR.3 U_SENSOR.9 U_SENSOR.13 U_SENSOR.15 U_SENSOR.16 U_USB_UART.4
copper on no net:
  other v2: 37.2,54.4

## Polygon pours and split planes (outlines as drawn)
GND on Bottom (solid): 117.1,85.1 25.7,85.1 25.7,25.7 117.1,25.7
GND on Bottom (solid): 65.633,76.593 65.357,76.593 65.39,76.565 65.484,76.452 65.495,76.43 65.506,76.452 65.6,76.565
GND on Bottom (solid): 65.495,75.64 65.484,75.618 65.399,75.515 65.591,75.515 65.506,75.618
GND on Bottom (solid): 65.61,75.496 65.61,75.304 65.713,75.389 65.735,75.4 65.713,75.411
GND on Bottom (solid): 69.305,75.64 69.294,75.618 69.2,75.505 69.087,75.411 69.065,75.4 69.087,75.389 69.2,75.295 69.294,75.182 69.305,75.16 69.316,75.182 69.41,75.295 69.523,75.389 69.545,75.4 69.523,75.411 69.41,75.505 69.316,75.618
GND on Bottom (solid): 68.035,75.64 68.024,75.618 67.93,75.505 67.817,75.411 67.795,75.4 67.817,75.389 67.93,75.295 68.024,75.182 68.035,75.16 68.046,75.182 68.14,75.295 68.253,75.389 68.275,75.4 68.253,75.411 68.14,75.505 68.046,75.618
GND on Bottom (solid): 66.765,75.64 66.754,75.618 66.66,75.505 66.547,75.411 66.525,75.4 66.547,75.389 66.66,75.295 66.754,75.182 66.765,75.16 66.776,75.182 66.87,75.295 66.983,75.389 67.005,75.4 66.983,75.411 66.87,75.505 66.776,75.618

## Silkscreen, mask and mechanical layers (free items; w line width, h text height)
Top Overlay:
  text "3V3 • SWD • 2L" at 43.4,83.4 h0.48
  text "I2C 0x18 • USB-C UART" at 98.4,83.4 h0.5
  text "MSPM0G3507SPMR + CH340N" at 60.4,29.9 h0.52
  text "LIS3DHTR" at 101.4,29.9 h0.55
  text "QUICK CONFIGURE • ADAFRUIT SENSOR" at 76.4,27.4 h0.65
